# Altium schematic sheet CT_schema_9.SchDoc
size 278 x 170 mm
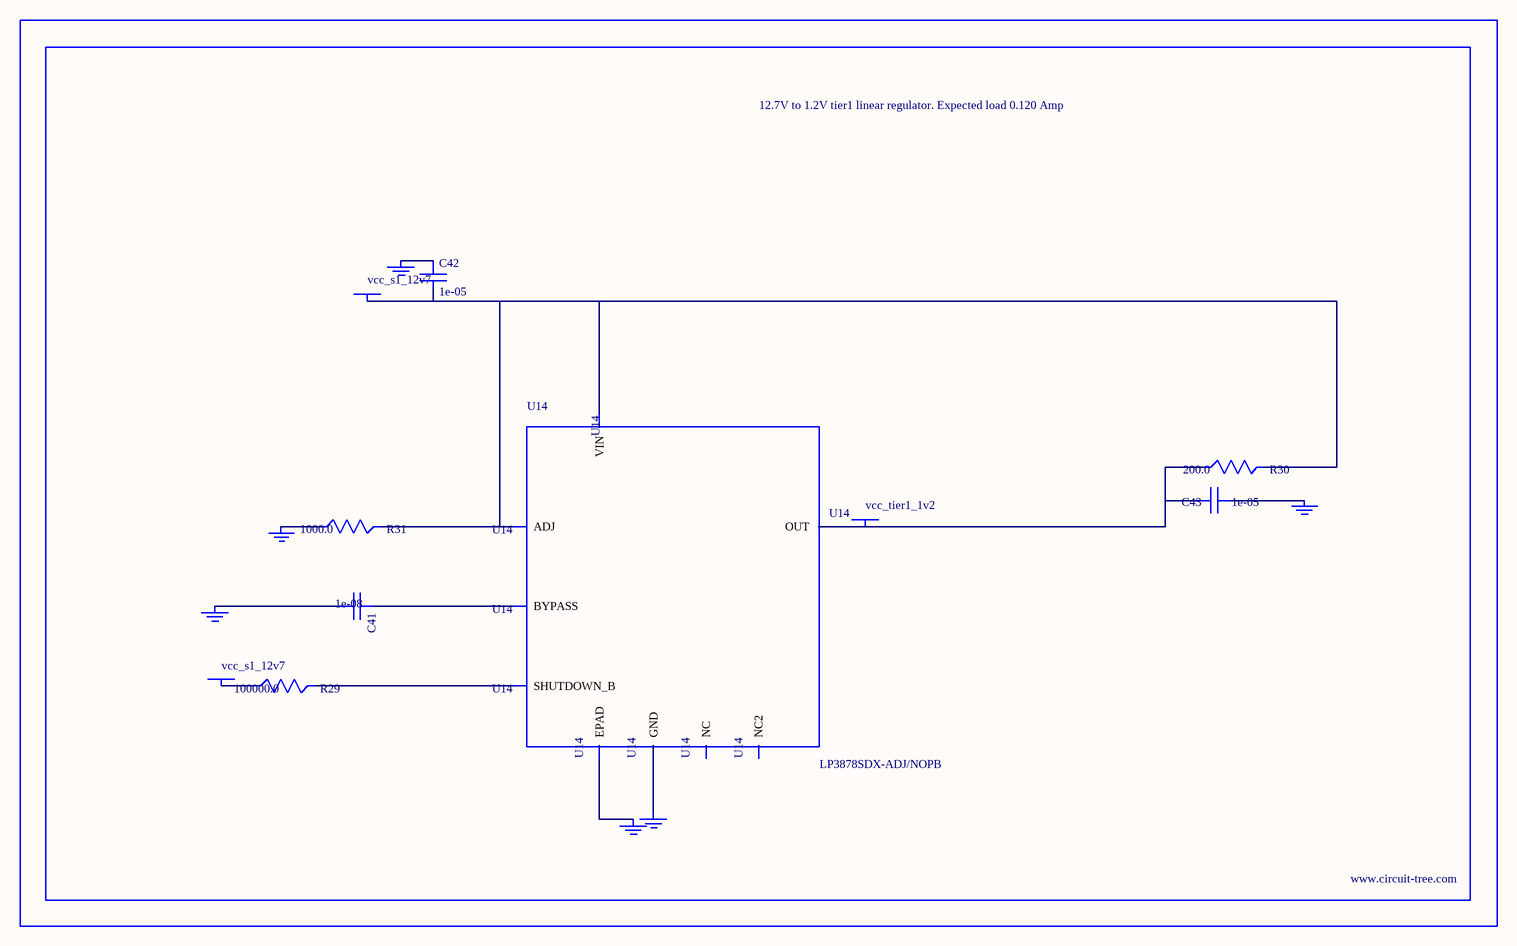
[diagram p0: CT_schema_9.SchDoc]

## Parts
BORDER8  (no value)
C41  1e-08  [C0402]
C42  1e-05  [C1210]
C43  1e-05  [C0805]
GND_INSTANCE_8_0  (no value)
GND_INSTANCE_8_1  (no value)
GND_INSTANCE_8_2  (no value)
GND_INSTANCE_8_3  (no value)
GND_INSTANCE_8_4  (no value)
GND_INSTANCE_8_5  (no value)
POWER_INSTANCE_8_0  vcc_s1_12v7
POWER_INSTANCE_8_1  vcc_s1_12v7
POWER_INSTANCE_8_2  vcc_tier1_1v2
R29  100000.0  [R0603]
R30  200.0  [R0603]
R31  1000.0  [R0603]
U14  LP3878SDX-ADJ/NOPB  [WSON-8]

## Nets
NetC41_1: C41.1 U14.1(BYPASS)
NetC41_2: C41.2 GND_INSTANCE_8_0.0(GND)
NetC42_1: C42.1 GND_INSTANCE_8_1.0(GND)
NetC42_2: C42.2 POWER_INSTANCE_8_0.0(PWR) R30.2 R31.2 U14.4(VIN) U14.6(ADJ)
NetC43_1: C43.1 GND_INSTANCE_8_2.0(GND)
NetC43_2: C43.2 POWER_INSTANCE_8_2.0(PWR) R30.1 U14.5(OUT)
NetGND_INSTANCE_8_3_0: GND_INSTANCE_8_3.0(GND) R31.1
NetGND_INSTANCE_8_4_0: GND_INSTANCE_8_4.0(GND) U14.PAD(EPAD)
NetGND_INSTANCE_8_5_0: GND_INSTANCE_8_5.0(GND) U14.3(GND)
NetPOWER_INSTANCE_8_1_0: POWER_INSTANCE_8_1.0(PWR) R29.1
NetR29_2: R29.2 U14.8(SHUTDOWN_B)

Not connected (* = marked no-connect by the designer): U14 2(NC) 7(NC2)

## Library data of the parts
BORDER8 = BORDER_PAGE8
C41 = C0402C103K3RAC
C42 = C1210C106K5PACTU
C43 = GRM219R60J106ME19D
GND_INSTANCE_8_0-GND_INSTANCE_8_5 = GND
POWER_INSTANCE_8_0-POWER_INSTANCE_8_2 = PWR
R29 = RC0603JR-07100KL
R30 = RC0603JR-07200RL
R31 = RC0603JR-071KL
